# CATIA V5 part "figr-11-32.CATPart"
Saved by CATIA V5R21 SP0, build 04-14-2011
Part number: Part1
Bounding box of the stored display mesh (mm): x -280 to 270, y -160 to 10, z 0 to 443
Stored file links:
  D:\CATIA V5R21 E-RESOURCES\CATIA-V5R21\catia-v5r21-prt\c11-catia-v5r21-prt\c11-catia-v5r21-figr-11-32.CATPart
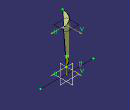
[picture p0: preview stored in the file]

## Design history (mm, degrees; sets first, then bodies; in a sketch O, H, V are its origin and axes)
Set1
  Plane1: type Offset, RefPlane xy-plane, Offset 443
  Sketch1 on Plane1, origin (0, 0, 443), H (1, 0, 0), V (0, 1, 0)
    arc A1 centre (51.3551, -160.9813) radius 171.358 from (40, 10) to (-120, -160) ccw
  Loft1: Sections (Sketch3; Sketch1)
  Sketch2 on zx-plane, origin (0, 0, 0), H (-1, 0, 0), V (0, 0, 1)
    line L1 (-270, 0) -> (280, 0)
    point P1 (-270, 0)
    coincidence: P1 H
    horizontal: L1 H
Body1 (main body)
  Sketch3 on Plane2, origin (0, 0, 67), H (1, 0, 0), V (0, 1, 0)
    point P1 (-100, 0)
    arc A1 centre (50, -150) radius 158.1139 from (0, 0) to (-100, -100) ccw
Set2
  Plane2: type Offset, RefPlane xy-plane, Offset 67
